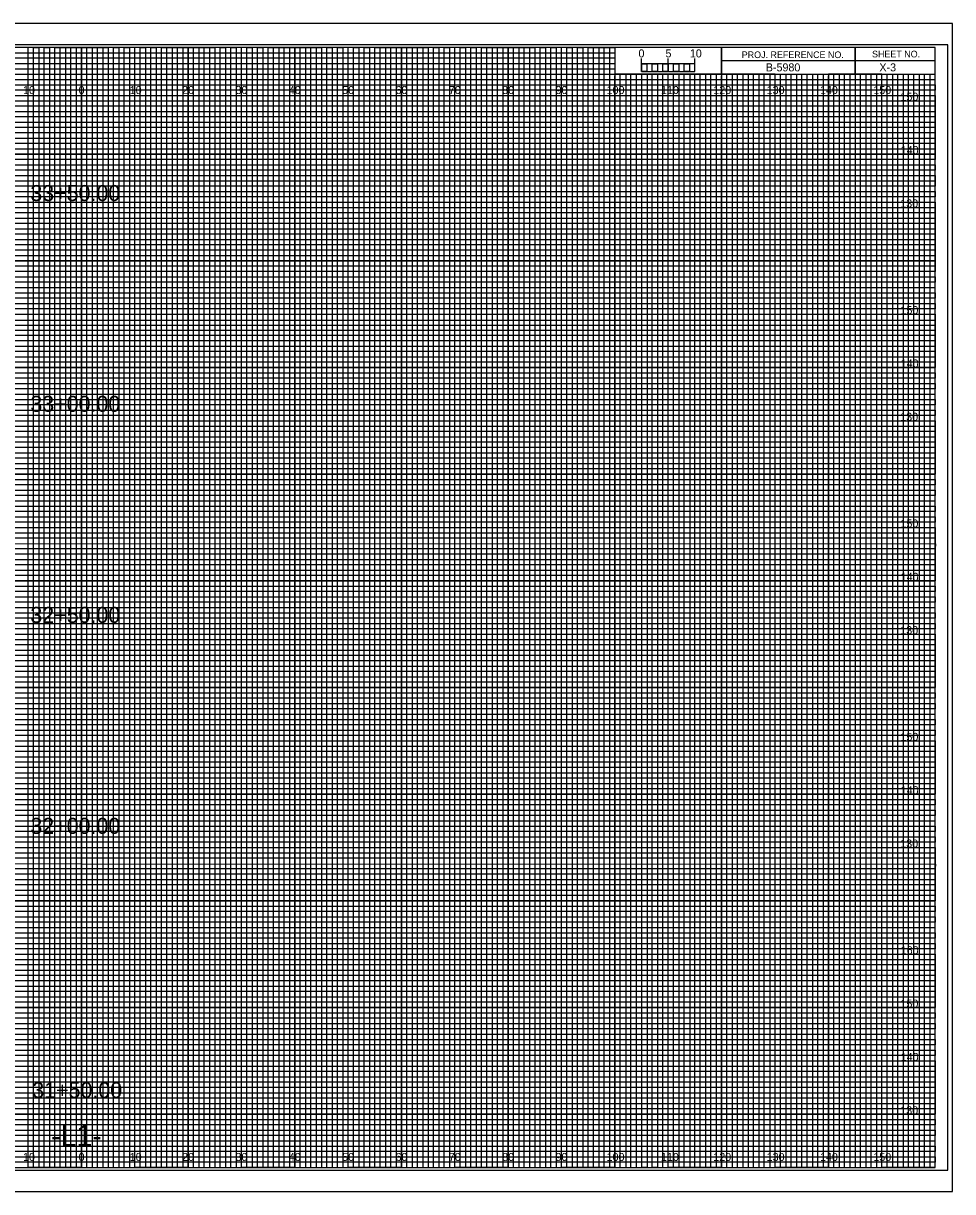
# Model space of a CAD drawing. Extents: x -13 to 323, y -5 to 3294.
# Drawn here: x 149.1 to 323.3, y 435.5 to 654.5 of the extents above; entities that cross this region are included whole.
import ezdxf

# ---------------------------------------------------------------- set-up
doc = ezdxf.new("R2010")
doc.units = 0
for name, color, linetype in [('Prop XS Alignment Label', 7, 'Continuous'), ('Prop XS Bar Scale Labels', 7, 'Continuous'), ('Prop XS Elevation Labels', 7, 'Continuous'), ('Prop XS Offset Labels', 7, 'Continuous'), ('Prop XS Project Number', 7, 'Continuous'), ('Prop XS Sheet Number', 7, 'Continuous'), ('Prop XS Station Labels', 7, 'Continuous'), ('Sheet Cross Section CELL', 7, 'Continuous'), ('Sheet Cross Section Grid Major CELL', 7, 'Continuous'), ('Sheet Cross Section Grid Middle CELL', 7, 'Continuous'), ('Sheet Cross Section Grid Minor 1 CELL', 7, 'Continuous'), ('Sheet Cross Section Grid Minor 2 CELL', 7, 'Continuous'), ('Sheet Cross Section Scale CELL', 7, 'Continuous'), ('Sheet Cutting Line CELL', 7, 'Continuous'), ('Sheet DOT Grid CELL', 7, 'Continuous'), ('Sheet Plot Border Inside CELL', 7, 'Continuous'), ('Sheet Plot Border Outside CELL', 7, 'Continuous')]:
    doc.layers.add(name, color=color, linetype=linetype)

msp = doc.modelspace()

# ---------------------------------------------------------------- linework, layer by layer
at = {"layer": 'Sheet Cross Section CELL'}
for p, q in [((305, 650), (305, 645)), ((305, 645), (305, 650)), ((280, 647.5), (280, 645)), ((320, 647.49), (280, 647.49)), ((280, 645), (320, 645))]:
    msp.add_line(p, q, dxfattribs=at)
for points in [[(320, 650), (0, 650), (0, 440), (320, 440)], [(280, 650), (260, 650), (260, 645.03), (280, 645.03)], [(320, 650), (280, 650), (280, 645), (320, 645)]]:
    msp.add_lwpolyline(points, close=True, dxfattribs=at)
at = {"layer": 'Sheet Cross Section Grid Major CELL'}
for p, q in [((150, 650), (140, 650)), ((150, 440), (150, 650)), ((170, 650), (160, 650)), ((160, 650), (160, 440)), ((170, 440), (170, 650)), ((190, 650), (180, 650)), ((180, 650), (180, 440)), ((190, 440), (190, 650)), ((210, 650), (200, 650)), ((200, 650), (200, 440)), ((210, 440), (210, 650)), ((230, 650), (220, 650)), ((220, 650), (220, 440)), ((230, 440), (230, 650)), ((250, 650), (240, 650)), ((240, 650), (240, 440)), ((250, 440), (250, 650)), ((260, 650), (260, 440)), ((270, 440), (270, 645)), ((290, 645), (280, 645)), ((280, 645), (280, 440)), ((290, 440), (290, 645)), ((310, 645), (300, 645)), ((300, 645), (300, 440)), ((310, 440), (310, 645)), ((160, 440), (150, 440)), ((180, 440), (170, 440)), ((200, 440), (190, 440)), ((220, 440), (210, 440)), ((240, 440), (230, 440)), ((260, 440), (250, 440)), ((280, 440), (270, 440)), ((300, 440), (290, 440)), ((320, 440), (310, 440)), ((320, 440), (320, 440))]:
    msp.add_line(p, q, dxfattribs=at)
for points in [[(0, 640), (320, 640), (320, 630), (0, 630)], [(0, 620), (320, 620), (320, 610), (0, 610)], [(0, 600), (320, 600), (320, 590), (0, 590)], [(0, 580), (320, 580), (320, 570), (0, 570)], [(0, 560), (320, 560), (320, 550), (0, 550)], [(0, 540), (320, 540), (320, 530), (0, 530)], [(0, 520), (320, 520), (320, 510), (0, 510)], [(0, 500), (320, 500), (320, 490), (0, 490)], [(0, 480), (320, 480), (320, 470), (0, 470)], [(0, 460), (320, 460), (320, 450), (0, 450)]]:
    msp.add_lwpolyline(points, dxfattribs=at)
at = {"layer": 'Sheet Cross Section Grid Middle CELL'}
for points in [[(145, 440), (155, 440), (155, 650), (165, 650), (165, 440), (175, 440), (175, 650), (185, 650), (185, 440), (195, 440), (195, 650), (205, 650), (205, 440), (215, 440), (215, 650), (225, 650), (225, 440), (235, 440), (235, 650), (245, 650), (245, 440), (255, 440), (255, 650), (259.93, 650), (260, 650), (260, 645), (264.99, 645), (264.99, 440), (275, 440), (275, 645), (285, 645), (285, 440), (295, 440), (295, 645), (305, 645), (305, 440), (315, 440), (315, 645)], [(0, 645), (275, 645)], [(0, 625), (320, 625), (320, 635), (0, 635)], [(0, 605), (320, 605), (320, 615), (0, 615)], [(0, 585), (320, 585), (320, 595), (0, 595)], [(0, 565), (320, 565), (320, 575), (0, 575)], [(0, 545), (320, 545), (320, 555), (0, 555)], [(0, 525), (320, 525), (320, 535), (0, 535)], [(0, 505), (320, 505), (320, 515), (0, 515)], [(0, 485), (320, 485), (320, 495), (0, 495)], [(0, 465), (320, 465), (320, 475), (0, 475)], [(0, 445), (320, 445), (320, 455), (0, 455)]]:
    msp.add_lwpolyline(points, dxfattribs=at)
at = {"layer": 'Sheet Cross Section Grid Minor 1 CELL'}
for p, q in [((0, 649), (260, 649)), ((260, 649), (260, 647.98)), ((260, 647.98), (0, 647.98)), ((0, 647), (260, 647)), ((260, 647), (260, 645.89)), ((260, 645.89), (0, 645.89)), ((0, 644), (320, 644))]:
    msp.add_line(p, q, dxfattribs=at)
for points in [[(0, 643), (270, 643), (320, 643), (320, 642), (0, 642)], [(0, 641), (320, 641), (320, 639), (0, 639)], [(0, 638), (320, 638), (320, 637), (0, 636.98)], [(0, 636), (320, 636), (320, 634), (0, 634)], [(0, 633), (320, 633), (320, 632), (0, 632)], [(0, 631), (320, 631), (320, 629), (0, 629)], [(0, 628), (320, 628), (320, 627), (0, 627)], [(0, 626), (320, 626), (320, 624), (0, 624)], [(0, 623), (320, 623), (320, 622), (0, 622)], [(0, 621), (320, 621), (320, 619), (0, 619)], [(0, 618), (320, 618), (320, 617), (0, 617)], [(0, 616), (320, 616), (320, 613.95), (320, 613), (320, 612), (0, 612)], [(0, 614), (320, 614), (320, 613), (0, 613)], [(0, 611), (320, 611), (320, 609), (0, 609.03)], [(0, 609.03), (320, 609), (320, 608), (0, 608)], [(0, 607), (320, 607), (320, 606), (0, 606)], [(0, 604), (320, 604), (320, 603), (0, 603)], [(0, 602), (320, 602), (320, 601), (0, 601)], [(-0.07, 598.89), (320, 598.89), (320, 597.88), (-0.07, 597.88)], [(0, 597), (320, 597), (320, 596), (0, 596)], [(0, 594), (320, 594), (320, 593), (0, 593)], [(0, 592), (320, 592), (320, 591), (0, 591)], [(0, 589), (320, 589), (320, 588), (0, 588)], [(0, 587), (320, 587), (320, 586), (0, 586)], [(0, 584), (320, 584), (320, 583), (0, 583)], [(0, 582), (320, 582), (320, 581), (0, 581)], [(0, 579), (320, 579), (319.99, 577.98), (0, 578)], [(0, 577), (320, 577), (320, 576), (0, 576)], [(0, 574), (320, 574), (320, 573), (0, 573)], [(0, 572), (320, 572), (320, 571), (0, 571)], [(0, 569), (320, 569), (320, 568), (0, 568)], [(0, 567), (320, 567), (320, 566), (0, 566)], [(0, 564), (320, 564), (320, 563), (0, 563)], [(0, 562), (320, 562), (320, 561), (0, 561)], [(0, 559), (320, 559), (320, 558), (0, 558)], [(0, 556.99), (320.07, 556.91), (320, 556), (0, 556)], [(0, 554), (320, 554), (320, 553), (0, 553)], [(0, 552), (320, 552), (320, 551), (0, 551)], [(0, 549), (320, 549), (320, 548), (0, 548)], [(0, 547), (320, 547), (320, 546), (0, 546)], [(0, 544), (320, 544), (320, 543), (0, 543)], [(0, 542), (320, 542), (320, 541), (0, 541)], [(0, 539), (320, 539), (320, 538), (0, 538)], [(0, 537), (320, 537), (320, 536), (0, 536)], [(0, 534), (320, 534), (320, 533), (0, 533)], [(0, 532), (320, 532), (320, 531), (0, 531)], [(0, 529), (320, 529), (320, 528), (0, 528)], [(0, 527), (320, 527), (320, 526), (0, 526)], [(0, 524), (320, 524), (320, 523), (0, 523)], [(0, 522), (320, 522), (320, 521), (0, 521)], [(0, 519), (320, 519), (319.99, 517.98), (0, 518)], [(0, 517), (320, 517), (320, 516), (0, 516)], [(0, 514), (320, 514), (320, 513), (0, 513)], [(0, 512), (320, 512), (320, 511), (0, 511)], [(0, 509), (320, 509), (320, 508), (0, 508)], [(0, 507), (320, 507), (320, 506), (0, 506)], [(0, 504), (320, 504), (320, 503), (0, 503)], [(0, 502), (320, 502), (320, 501), (0, 501)], [(0, 499), (320, 499), (320, 498), (0, 498)], [(0, 496.99), (320.07, 496.91), (320, 496), (0, 496)], [(0, 494), (320, 494), (320, 493), (0, 493)], [(0, 492), (320, 492), (320, 491), (0, 491)], [(0, 489), (320, 489), (320, 488), (0, 488)], [(0, 487), (320, 487), (320, 486), (0, 486)], [(0, 484), (320, 484), (320, 483), (0, 483)], [(0, 482), (320, 482), (320, 481), (0, 481)], [(0, 479), (320, 479), (320, 478), (0, 478)], [(0, 477), (320, 477), (320, 476), (0, 476)], [(0, 474), (320, 474), (320, 473), (0, 473)], [(0, 472), (320, 472), (320, 471), (0, 471)], [(0, 469), (320, 469), (320, 468), (0, 468)], [(0, 467), (320, 467), (320, 466), (0, 466)], [(0, 464), (320, 464), (320, 463), (0, 463)], [(0, 462), (320, 462), (320, 461), (0, 461)], [(0, 459), (320, 459), (320, 458), (0, 458)], [(0, 457), (320, 457), (320, 456), (0, 456)], [(0, 454), (320, 454), (320, 453), (0, 453)], [(0, 452), (320, 452), (320, 451), (0, 451)], [(0, 449), (320, 449), (320, 448), (0, 448)], [(0, 447), (320, 447), (320, 446), (0, 446)], [(0, 444), (320, 444), (320, 443), (0, 443)], [(0, 442), (320, 442), (320, 441), (0, 441)]]:
    msp.add_lwpolyline(points, dxfattribs=at)
at = {"layer": 'Sheet Cross Section Grid Minor 2 CELL'}
for p, q in [((267, 645), (266.01, 645)), ((266.01, 645), (266.01, 440)), ((267, 440), (267, 645)), ((269, 645), (268, 645)), ((268, 645), (268, 440)), ((269, 440), (269, 645)), ((266.01, 440), (265, 440)), ((268, 440), (267, 440))]:
    msp.add_line(p, q, dxfattribs=at)
for points in [[(150, 440), (151, 440), (151, 650), (152, 650), (152, 440)], [(152, 440), (153, 440), (153, 650), (154, 650), (154, 440)], [(155, 440), (156, 440), (156, 650), (157, 650), (157, 440)], [(157, 440), (158, 440), (158, 650), (159, 650), (159, 440)], [(160, 440), (161, 440), (161, 650), (162, 650), (162, 440)], [(162, 440), (163, 440), (163, 650), (164, 650), (164, 440)], [(165, 440), (166, 440), (166, 650), (167, 650), (167, 440)], [(167, 440), (168, 440), (168, 650), (169, 650), (169, 440)], [(170, 440), (171, 440), (171, 650), (172, 650), (172, 440)], [(172, 440), (173, 440), (173, 650), (174, 650), (174, 440)], [(175, 440), (176, 440), (176, 650), (177, 650), (177, 440)], [(177, 440), (178, 440), (178, 650), (179, 650), (179, 440)], [(180, 440), (181, 440), (181, 650), (182, 650), (182, 440)], [(182, 440), (183, 440), (183, 650), (184, 650), (184, 440)], [(185, 440), (186, 440), (186, 650), (187, 650), (187, 440)], [(187, 440), (188, 440), (188, 650), (189, 650), (189, 440)], [(190, 440), (191, 440), (191, 650), (192, 650), (192, 440)], [(192, 440), (193, 440), (193, 650), (194, 650), (194, 440)], [(195, 440), (196, 440), (196, 650), (197, 650), (197, 440)], [(197, 440), (198, 440), (198, 650), (199, 650), (199, 440)], [(200, 440), (201, 440), (201, 650), (202, 650), (202, 440)], [(202, 440), (203, 440), (203, 650), (204, 650), (204, 440)], [(205, 440), (206, 440), (206, 650), (207, 650), (207, 440)], [(207, 440), (208, 440), (208, 650), (209, 650), (209, 440)], [(210, 440), (211, 440), (211, 650), (212, 650), (212, 440)], [(212, 440), (213, 440), (213, 650), (214, 650), (214, 440)], [(215, 440), (216, 440), (216, 650), (217, 650), (217, 440)], [(217, 440), (218, 440), (218, 650), (219, 650), (219, 440)], [(220, 440), (221, 440), (221, 650), (222, 650), (222, 440)], [(222, 440), (223, 440), (223, 650), (224, 650), (224, 440)], [(225, 440), (226, 440), (226, 650), (227, 650), (227, 440)], [(227, 440), (228, 440), (228, 650), (229, 650), (229, 440)], [(230, 440), (231, 440), (231, 650), (232, 650), (232, 440)], [(232, 440), (233, 440), (233, 650), (234, 650), (234, 440)], [(235, 440), (236, 440), (236, 650), (237, 650), (237, 440)], [(237, 440), (238, 440), (238, 650), (239, 650), (239, 440)], [(240, 440), (241, 440), (241, 650), (242, 650), (242, 440)], [(242, 440), (243, 440), (243, 650), (244, 650), (244, 440)], [(245, 440), (246, 440), (246, 650), (247, 650), (247, 440)], [(247, 440), (248, 440), (248, 650), (249, 650), (249, 440)], [(250, 440), (251, 440), (251, 650), (252, 650), (252, 440)], [(252, 440), (253, 440), (253, 650), (254, 650), (254, 440)], [(255, 440), (256, 440), (256, 650), (257, 650), (257, 440)], [(257, 440), (258, 440), (258, 650), (259, 650), (259, 440)], [(260, 440), (261, 440), (261, 645), (262.02, 645), (262.02, 440)], [(262, 440), (263, 440), (263, 645), (263.99, 645), (263.99, 440)], [(270, 440), (270.98, 440), (270.98, 645), (272, 645), (272, 440)], [(272, 440), (273, 440), (273, 645), (274.05, 645), (274.05, 440)], [(275, 440), (276, 440), (276, 645), (277, 645), (277, 440)], [(277, 440), (278, 440), (278, 645), (279, 645), (279, 440)], [(280, 440), (281, 440), (281, 645), (282, 645), (282, 440)], [(282, 440), (283, 440), (283, 645), (284, 645), (284, 440)], [(285, 440), (286, 440), (286, 645), (287, 645), (287, 440)], [(287, 440), (288, 440), (288, 645), (289, 645), (289, 440)], [(290, 440), (291, 440), (291, 645), (292, 645), (292, 440)], [(292, 440), (293, 440), (293, 645), (294, 645), (294, 440)], [(295, 440), (296, 440), (296, 645), (297, 645), (297, 440)], [(297, 440), (298, 440), (298, 645), (299, 645), (299, 440)], [(300, 440), (301, 440), (301, 645), (302, 645), (302, 440)], [(302, 440), (303, 440), (303, 645), (304, 645), (304, 440)], [(305, 440), (306, 440), (306, 645), (307, 645), (307, 440)], [(307, 440), (308, 440), (308, 645), (309, 645), (309, 440)], [(310, 440), (311, 440), (311, 645), (312, 645), (312, 440)], [(312, 440), (313, 440), (313, 645), (314, 645), (314, 440)], [(315, 440), (316, 440), (316, 645), (317, 645), (317, 440)], [(317, 440), (318, 440), (318, 645), (319, 645), (319, 440)]]:
    msp.add_lwpolyline(points, dxfattribs=at)
at = {"layer": 'Sheet Cross Section Scale CELL'}
for p, q in [((265, 645.49), (265, 647.9)), ((265, 646.9), (265, 647.9)), ((270, 645.49), (270, 647.9)), ((275, 645.49), (275, 647.9)), ((275, 646.9), (275, 647.9))]:
    msp.add_line(p, q, dxfattribs=at)
for points in [[(275, 646.9), (265, 646.9), (265, 645.49), (275, 645.49)], [(265, 646.9), (266, 646.9), (266, 645.49), (265, 645.49)], [(267, 646.9), (268, 646.9), (268, 645.49), (267, 645.49)], [(269, 646.9), (270, 646.9), (270, 645.49), (269, 645.49)], [(271, 646.9), (272, 646.9), (272, 645.49), (271, 645.49)], [(273, 646.9), (274, 646.9), (274, 645.49), (273, 645.49)]]:
    msp.add_lwpolyline(points, close=True, dxfattribs=at)
at = {"layer": 'Sheet Cutting Line CELL'}
for p, q in [((323.3, 654.5), (-13.4, 654.5)), ((-13.4, 435.5), (323.3, 435.5))]:
    msp.add_line(p, q, dxfattribs=at)
at = {"layer": 'Sheet DOT Grid CELL'}
for p, q in [((150, 440), (150, 650)), ((160, 440), (160, 650)), ((170, 440), (170, 650)), ((180, 440), (180, 650)), ((190, 440), (190, 650)), ((200, 440), (200, 650)), ((210, 440), (210, 650)), ((220, 440), (220, 650)), ((230, 440), (230, 650)), ((240, 440), (240, 650)), ((250, 440), (250, 650)), ((260, 440), (260, 644.69)), ((270, 440), (270, 644.69)), ((280, 440), (280, 644.69)), ((290, 440), (290, 644.69)), ((300, 440), (300, 644.69)), ((310, 440), (310, 644.69)), ((0, 640), (320, 640)), ((0, 630), (320, 630)), ((0, 620), (320, 620)), ((0, 610), (320, 610)), ((0, 600), (320, 600)), ((0, 590), (320, 590)), ((0, 580), (320, 580)), ((0, 570), (320, 570)), ((0, 560), (320, 560)), ((0, 550), (320, 550)), ((0, 540), (320, 540)), ((0, 530), (320, 530)), ((0, 520), (320, 520)), ((0, 510), (320, 510)), ((0, 500), (320, 500)), ((0, 490), (320, 490)), ((0, 480), (320, 480)), ((0, 470), (320, 470)), ((0, 460), (320, 460)), ((0, 450), (320, 450))]:
    msp.add_line(p, q, dxfattribs=at)
at = {"layer": 'Sheet Plot Border Inside CELL'}
msp.add_lwpolyline([(-10.8, 439.5), (322.4, 439.5), (322.4, 650.5), (-10.8, 650.5)], close=True, dxfattribs=at)
at = {"layer": 'Sheet Plot Border Outside CELL'}
msp.add_lwpolyline([(-13.4, 435.5), (323.3, 435.5), (323.3, 654.5), (-13.4, 654.5)], close=True, dxfattribs=at)

# ---------------------------------------------------------------- texts
at = {"layer": 'Prop XS Alignment Label'}
msp.add_text('-L1-', height=4, dxfattribs=at).set_placement((154.28, 444))
at = {"layer": 'Prop XS Bar Scale Labels'}
for s, p in [('5', (269.47, 648.12)), ('10', (274.04, 648.12))]:
    msp.add_text(s, height=1.5, dxfattribs=at).set_placement(p)
at = {"layer": 'Prop XS Elevation Labels'}
for s, p in [('150', (313.52, 640)), ('140', (313.57, 630)), ('130', (313.49, 620)), ('150', (313.52, 600)), ('140', (313.57, 590)), ('130', (313.49, 580)), ('150', (313.52, 560)), ('140', (313.57, 550)), ('130', (313.49, 540)), ('150', (313.52, 520)), ('140', (313.57, 510)), ('130', (313.49, 500)), ('160', (313.57, 480)), ('150', (313.52, 470)), ('140', (313.57, 460)), ('130', (313.49, 450))]:
    msp.add_text(s, height=1.5, dxfattribs=at).set_placement(p)
at = {"layer": 'Prop XS Offset Labels'}
for s, p in [('10', (149.04, 641.25)), ('0', (159.45, 641.25)), ('0', (159.45, 641.25)), ('10', (169.04, 641.25)), ('20', (178.86, 641.25)), ('30', (188.86, 641.25)), ('40', (198.86, 641.25)), ('50', (208.86, 641.25)), ('60', (218.86, 641.25)), ('70', (228.86, 641.25)), ('80', (238.86, 641.25)), ('90', (248.86, 641.25)), ('100', (258.44, 641.25)), ('110', (268.62, 641.25)), ('120', (278.44, 641.25)), ('130', (288.44, 641.25)), ('140', (298.44, 641.25)), ('150', (308.44, 641.25)), ('10', (149.04, 441.25)), ('0', (159.45, 441.25)), ('0', (159.45, 441.25)), ('10', (169.04, 441.25)), ('20', (178.86, 441.25)), ('30', (188.86, 441.25)), ('40', (198.86, 441.25)), ('50', (208.86, 441.25)), ('60', (218.86, 441.25)), ('70', (228.86, 441.25)), ('80', (238.86, 441.25)), ('90', (248.86, 441.25)), ('100', (258.44, 441.25)), ('110', (268.62, 441.25)), ('120', (278.44, 441.25)), ('130', (288.44, 441.25)), ('140', (298.44, 441.25)), ('150', (308.44, 441.25))]:
    msp.add_text(s, height=1.5, dxfattribs=at).set_placement(p)
at = {"layer": 'Prop XS Project Number'}
msp.add_text('B-5980', height=1.5, dxfattribs=at).set_placement((288.28, 645.5))
at = {"layer": 'Prop XS Sheet Number'}
msp.add_text('X-3', height=1.5, dxfattribs=at).set_placement((309.57, 645.5))
at = {"layer": 'Prop XS Station Labels'}
for s, p in [('33+50.00', (150.41, 621.19)), ('33+00.00', (150.41, 581.69)), ('32+50.00', (150.41, 542.11)), ('32+00.00', (150.41, 502.57)), ('31+50.00', (150.77, 453.04))]:
    msp.add_text(s, height=3, dxfattribs=at).set_placement(p)
at = {"layer": 'Sheet Cross Section CELL'}
for s, p in [('PROJ. REFERENCE NO.', (283.77, 647.99)), ('SHEET NO.', (308.19, 648.12))]:
    msp.add_text(s, height=1.25, dxfattribs=at).set_placement(p)
at = {"layer": 'Sheet Cross Section Scale CELL'}
msp.add_text('0', height=1.5, dxfattribs=at).set_placement((264.41, 648.12))

doc.saveas('drawing.dxf')
